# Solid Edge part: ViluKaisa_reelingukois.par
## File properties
Author: kaisa
Template: iso metric part.par
Last saved by: kaisa
Revision: 9
Application: Solid Edge
Density: 2595.000 kg/m^3
Accuracy: 0.990
Username: kaisa
Material: Glass, general industrial
Face Style: White (glass)
Fill Style: ANSI36(Marble)
Virtual Style: ANSI36(Marble)
Grouping: Non-metals\Generic Glass Fibers
LibraryName: Materials
Coef. of Thermal Exp: 0.0
Thermal Conductivity: 0.0
Specific Heat: 0.0
Modulus of Elasticity: 0.0
Poisson's Ratio: 0.23
Yield Stress: 0.0
Ultimate Stress: 0.0
Elongation: 0.0
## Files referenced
C:\Users\kaisa\Documents\ViluKaisa_reelingupost.par
iduk.asm
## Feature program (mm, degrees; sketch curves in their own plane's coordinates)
swept protrusion "SweptProtrusion_7"
Other named dimensions: "KeypointCurve_2": EndDerivMagnitude = -6.5805 mm
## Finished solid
Body 1: solid body, 3 faces, 2 edges, 0 vertices.
  Faces by surface: plane 2, spline 1
  Edges by curve: circle 2
Bounding box of the edges (mm; curved faces can reach further): 212.496 x 165.660 x 28.378, from (-1.1641, -0.9993, -27.3783) to (211.3317, 164.6608, 1).
Planar faces by outward normal: oblique 2
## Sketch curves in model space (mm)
circle centre (210.3518, 164.4156, -26.3886) radius 2
circle centre (200.8853, 120.8879, -19.9782) radius 2
circle centre (88.8047, 0.7283, -1.2184) radius 2
circle centre (188.2611, 78.1564, -13.6438) radius 2
circle centre (167.3164, 38.8913, -7.7077) radius 2
circle centre (132.2772, 11.6802, -3.3398) radius 2
circle centre (43.8615, -1.1823, -0.3859) radius 2
circle centre (-1.1257, 0, 0) radius 2
circle centre (210.3518, 164.4156, -26.3886) radius 1
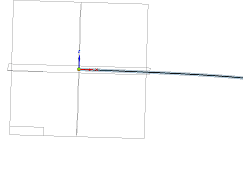
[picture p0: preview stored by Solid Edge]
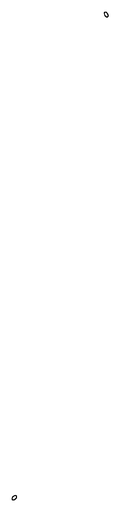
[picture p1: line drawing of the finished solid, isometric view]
